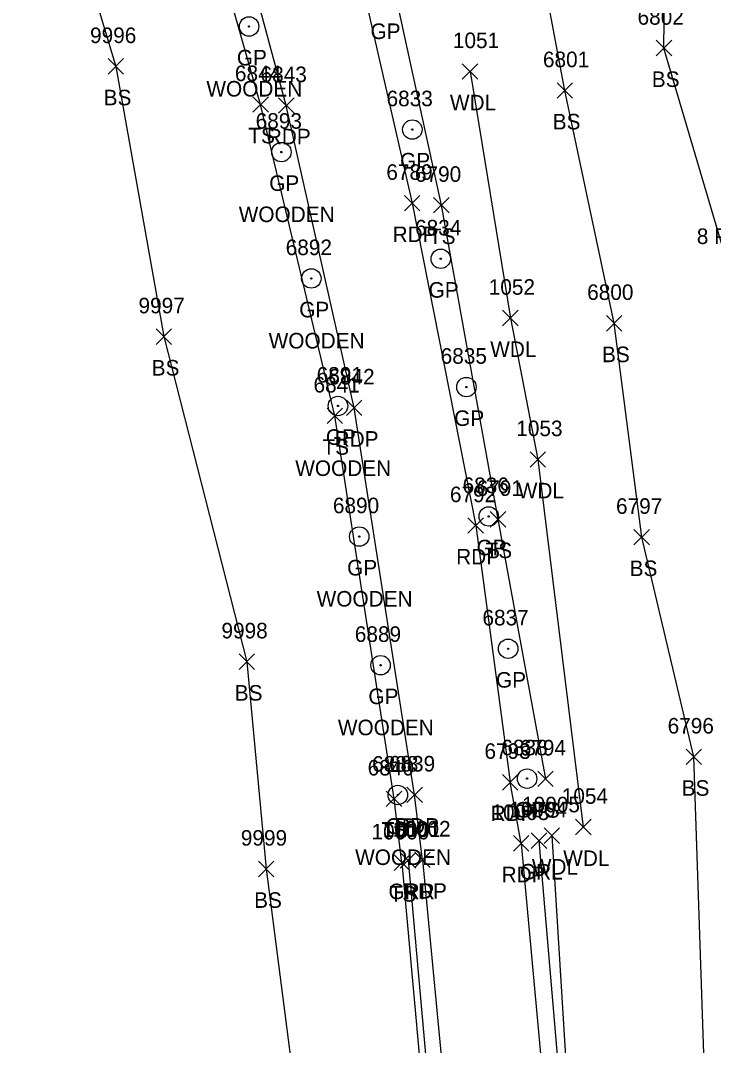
# Model space of a CAD drawing. Extents: x 1769141 to 1770817, y 735471 to 742405.
# Drawn here: x 1770054.4 to 1770143.6, y 740677.5 to 740809.3 of the extents above; entities that cross this region are included whole.
import ezdxf

# ---------------------------------------------------------------- set-up
doc = ezdxf.new("R2010")
doc.units = 0
for name, color, linetype in [('D_C', 7, 'Continuous'), ('L_A', 7, 'Continuous'), ('L_I', 7, 'Continuous'), ('L_TIC', 7, 'Continuous'), ('LAWA', 7, 'Continuous'), ('LELB', 7, 'Continuous'), ('P_A', 7, 'Continuous'), ('P_I', 7, 'Continuous'), ('P_TIC', 7, 'Continuous'), ('PET', 7, 'Continuous'), ('R_A', 7, 'Continuous'), ('R_C', 7, 'Continuous'), ('R_I', 7, 'Continuous'), ('R_TIC', 7, 'Continuous'), ('RGP', 7, 'Continuous'), ('RGR', 7, 'Continuous')]:
    doc.layers.add(name, color=color, linetype=linetype)

msp = doc.modelspace()

# ---------------------------------------------------------------- linework, layer by layer
at = {"layer": 'L_TIC'}
for points in [[(1770136.19, 740804.72), (1770138.19, 740806.72)], [(1770138.19, 740804.72), (1770136.19, 740806.72)], [(1770065.7, 740802.36), (1770067.7, 740804.36)], [(1770067.7, 740802.36), (1770065.7, 740804.36)], [(1770111.26, 740801.71), (1770113.26, 740803.71)], [(1770113.26, 740801.71), (1770111.26, 740803.71)], [(1770123.45, 740799.26), (1770125.45, 740801.26)], [(1770125.45, 740799.26), (1770123.45, 740801.26)], [(1770084.33, 740797.47), (1770086.33, 740799.47)], [(1770086.33, 740797.47), (1770084.33, 740799.47)], [(1770107.56, 740784.52), (1770109.56, 740786.52)], [(1770109.56, 740784.52), (1770107.56, 740786.52)], [(1770116.44, 740770.01), (1770118.44, 740772.01)], [(1770118.44, 740770.01), (1770116.44, 740772.01)], [(1770129.79, 740769.34), (1770131.79, 740771.34)], [(1770131.79, 740769.34), (1770129.79, 740771.34)], [(1770071.88, 740767.62), (1770073.88, 740769.62)], [(1770073.88, 740767.62), (1770071.88, 740769.62)], [(1770093.87, 740757.44), (1770095.87, 740759.44)], [(1770095.87, 740757.44), (1770093.87, 740759.44)], [(1770119.98, 740751.83), (1770121.98, 740753.83)], [(1770121.98, 740751.83), (1770119.98, 740753.83)], [(1770114.84, 740744.15), (1770116.84, 740746.15)], [(1770116.84, 740744.15), (1770114.84, 740746.15)], [(1770133.34, 740741.84), (1770135.34, 740743.84)], [(1770135.34, 740741.84), (1770133.34, 740743.84)], [(1770082.55, 740725.83), (1770084.55, 740727.83)], [(1770084.55, 740725.83), (1770082.55, 740727.83)], [(1770140.03, 740713.6), (1770142.03, 740715.6)], [(1770142.03, 740713.6), (1770140.03, 740715.6)], [(1770120.96, 740710.78), (1770122.96, 740712.78)], [(1770122.96, 740710.78), (1770120.96, 740712.78)], [(1770101.49, 740708.21), (1770103.49, 740710.21)], [(1770103.49, 740708.21), (1770101.49, 740710.21)], [(1770125.82, 740704.57), (1770127.82, 740706.57)], [(1770127.82, 740704.57), (1770125.82, 740706.57)], [(1770121.78, 740703.47), (1770123.78, 740705.47)], [(1770123.78, 740703.47), (1770121.78, 740705.47)], [(1770102.5, 740699.99), (1770104.5, 740701.99)], [(1770104.5, 740699.99), (1770102.5, 740701.99)], [(1770085.04, 740699.19), (1770087.04, 740701.19)], [(1770087.04, 740699.19), (1770085.04, 740701.19)]]:
    msp.add_lwpolyline(points, dxfattribs=at)
at = {"layer": 'LAWA'}
for points in [[(1770112.26, 740802.71), (1770117.44, 740771.01), (1770120.98, 740752.83), (1770126.82, 740705.57)], [(1770122.78, 740704.47), (1770125.57, 740659.44), (1770128.91, 740609.51), (1770131.96, 740548.28), (1770134.59, 740515.3), (1770138.96, 740463.85), (1770139.39, 740413.76), (1770142.68, 740366.71)]]:
    msp.add_lwpolyline(points, dxfattribs=at)
at = {"layer": 'LELB'}
for points in [[(1770102.49, 740709.21), (1770094.87, 740758.44), (1770085.33, 740798.47), (1770075.52, 740832.9), (1770071.79, 740852.56), (1770072, 740876.01), (1770079.42, 740895.94), (1770093.05, 740914.5), (1770103.42, 740925.63), (1770113.67, 740937.45), (1770115.5, 740958.52), (1770111.47, 740971.26), (1770103.86, 740991.31), (1770100.12, 740990.08), (1770106.06, 740964.67), (1770081.1, 740972.36)], [(1770108.26, 740894.78), (1770100.32, 740878.33), (1770097.64, 740862.66), (1770097.24, 740845.39), (1770100.42, 740822.73), (1770108.56, 740785.52), (1770115.84, 740745.15), (1770121.96, 740711.78)], [(1770148.83, 740712.41), (1770150.08, 740742.88), (1770146.81, 740773.11), (1770137.19, 740805.72), (1770137.5, 740834.46), (1770138.56, 740856.82)], [(1770054.44, 740844.19), (1770066.7, 740803.36)], [(1770141.03, 740714.6), (1770134.34, 740742.84), (1770130.79, 740770.34), (1770124.45, 740800.26), (1770118.37, 740832.68)], [(1770066.7, 740803.36), (1770072.88, 740768.62), (1770083.55, 740726.83), (1770086.04, 740700.19), (1770091.3, 740659.33), (1770094.84, 740607.83), (1770101.29, 740550.76), (1770100.94, 740526.31), (1770108.94, 740460.58), (1770110.98, 740412.54), (1770110.87, 740385.04), (1770097.8, 740370.51)], [(1770143.11, 740653.52), (1770141.03, 740714.6)], [(1770103.5, 740700.99), (1770102.49, 740709.21)], [(1770103.5, 740700.99), (1770107.28, 740658.82), (1770110.09, 740608.58), (1770112.97, 740550.02), (1770115.09, 740514.48), (1770117.12, 740463.09), (1770118.41, 740412.76)]]:
    msp.add_lwpolyline(points, dxfattribs=at)
at = {"layer": 'P_TIC'}
for points in [[(1770087.63, 740797.34), (1770089.63, 740799.34)], [(1770089.63, 740797.34), (1770087.63, 740799.34)], [(1770103.81, 740784.78), (1770105.81, 740786.78)], [(1770105.81, 740784.78), (1770103.81, 740786.78)], [(1770096.35, 740758.47), (1770098.35, 740760.47)], [(1770098.35, 740758.47), (1770096.35, 740760.47)], [(1770111.98, 740743.34), (1770113.98, 740745.34)], [(1770113.98, 740743.34), (1770111.98, 740745.34)], [(1770116.42, 740710.34), (1770118.42, 740712.34)], [(1770118.42, 740710.34), (1770116.42, 740712.34)], [(1770104.13, 740708.72), (1770106.13, 740710.72)], [(1770106.13, 740708.72), (1770104.13, 740710.72)], [(1770117.83, 740702.48), (1770119.83, 740704.48)], [(1770119.83, 740702.48), (1770117.83, 740704.48)], [(1770105.14, 740700.36), (1770107.14, 740702.36)], [(1770107.14, 740700.36), (1770105.14, 740702.36)]]:
    msp.add_lwpolyline(points, dxfattribs=at)
at = {"layer": 'PET'}
for points in [[(1770105.13, 740709.72), (1770097.35, 740759.47), (1770088.63, 740798.34), (1770079.18, 740833.38), (1770075.73, 740850.43), (1770075.74, 740874.63), (1770082.21, 740893.72), (1770094.91, 740911.6)], [(1770105.78, 740897.9), (1770097.22, 740882.49), (1770093.23, 740863.22), (1770093.28, 740846.48), (1770097.27, 740818.78), (1770104.81, 740785.78), (1770112.98, 740744.34), (1770117.42, 740711.34)], [(1770118.83, 740703.48), (1770117.42, 740711.34)], [(1770106.14, 740701.36), (1770105.13, 740709.72)], [(1770118.83, 740703.48), (1770122.85, 740659.67), (1770125.57, 740609.37), (1770128.65, 740548.21), (1770130.22, 740515.08), (1770132.68, 740464.53), (1770135.18, 740413.13), (1770137.79, 740366.92)], [(1770106.14, 740701.36), (1770110.18, 740659.08), (1770112.94, 740608.4), (1770116.08, 740549.79), (1770117.88, 740514.91), (1770120.38, 740463.02), (1770123.02, 740413.12), (1770124.14, 740391.24), (1770126.21, 740354.16)]]:
    msp.add_lwpolyline(points, dxfattribs=at)
at = {"layer": 'R_TIC'}
for points in [[(1770120.12, 740702.83), (1770122.12, 740704.83)], [(1770122.12, 740702.83), (1770120.12, 740704.83)], [(1770103.28, 740700.3), (1770105.28, 740702.3)], [(1770105.28, 740700.3), (1770103.28, 740702.3)]]:
    msp.add_lwpolyline(points, dxfattribs=at)
at = {"layer": 'RGP'}
for p, q in [((1770083.84, 740808.49), (1770083.84, 740808.49)), ((1770104.83, 740795.24), (1770104.83, 740795.24)), ((1770088, 740792.35), (1770088, 740792.35)), ((1770108.49, 740778.63), (1770108.49, 740778.63)), ((1770091.85, 740776.1), (1770091.85, 740776.1)), ((1770111.79, 740762.14), (1770111.79, 740762.14)), ((1770095.27, 740759.71), (1770095.27, 740759.71)), ((1770114.66, 740745.51), (1770114.66, 740745.51)), ((1770098.01, 740742.92), (1770098.01, 740742.92)), ((1770117.16, 740728.5), (1770117.16, 740728.5)), ((1770100.75, 740726.38), (1770100.75, 740726.38)), ((1770119.59, 740711.8), (1770119.59, 740711.8)), ((1770102.97, 740709.7), (1770102.97, 740709.7))]:
    msp.add_line(p, q, dxfattribs=at)
for centre, radius in [((1770083.84, 740808.49), 1.25), ((1770083.84, 740808.49), 0.0833), ((1770104.83, 740795.24), 1.25), ((1770104.83, 740795.24), 0.0833), ((1770088, 740792.35), 1.25), ((1770088, 740792.35), 0.0833), ((1770108.49, 740778.63), 1.25), ((1770108.49, 740778.63), 0.0833), ((1770091.85, 740776.1), 1.25), ((1770091.85, 740776.1), 0.0833), ((1770111.79, 740762.14), 1.25), ((1770111.79, 740762.14), 0.0833), ((1770095.27, 740759.71), 1.25), ((1770095.27, 740759.71), 0.0833), ((1770114.66, 740745.51), 1.25), ((1770114.66, 740745.51), 0.0833), ((1770098.01, 740742.92), 1.25), ((1770098.01, 740742.92), 0.0833), ((1770117.16, 740728.5), 1.25), ((1770117.16, 740728.5), 0.0833), ((1770100.75, 740726.38), 1.25), ((1770100.75, 740726.38), 0.0833), ((1770119.59, 740711.8), 1.25), ((1770102.97, 740709.7), 1.25), ((1770119.59, 740711.8), 0.0833), ((1770102.97, 740709.7), 0.0833)]:
    msp.add_circle(centre, radius, dxfattribs=at)
at = {"layer": 'RGR'}
for points in [[(1770121.12, 740703.83), (1770124.89, 740659.66), (1770127.38, 740609.54), (1770130.69, 740548.36), (1770132.41, 740515.26), (1770135.66, 740464.82), (1770137.42, 740413.55), (1770140, 740367.83)], [(1770104.28, 740701.3), (1770108.06, 740659.13), (1770111.14, 740608.55), (1770114.23, 740549.9), (1770116.09, 740514.54), (1770118.42, 740463.29), (1770120.8, 740413.18)]]:
    msp.add_lwpolyline(points, dxfattribs=at)

# ---------------------------------------------------------------- texts
at = {"layer": 'D_C'}
msp.add_text('8 PLASTIC', height=2, dxfattribs=at).set_placement((1770141.42, 740780.53))
at = {"layer": 'L_A'}
for s, p in [('BS', (1770135.63, 740800.72)), ('BS', (1770065.14, 740798.36)), ('WDL', (1770109.67, 740797.71)), ('BS', (1770122.89, 740795.26)), ('TS', (1770083.74, 740793.47)), ('TS', (1770106.97, 740780.52)), ('WDL', (1770114.85, 740766.01)), ('BS', (1770129.23, 740765.34)), ('BS', (1770071.32, 740763.62)), ('TS', (1770093.28, 740753.44)), ('WDL', (1770118.39, 740747.83)), ('TS', (1770114.25, 740740.15)), ('BS', (1770132.78, 740737.84)), ('BS', (1770082, 740721.83)), ('BS', (1770139.47, 740709.6)), ('TS', (1770120.37, 740706.78)), ('TS', (1770100.89, 740704.21)), ('WDL', (1770124.24, 740700.57)), ('WDL', (1770120.2, 740699.47)), ('TS', (1770101.91, 740695.99)), ('BS', (1770084.49, 740695.19))]:
    msp.add_text(s, height=2, dxfattribs=at).set_placement(p)
at = {"layer": 'L_I'}
for s, p in [('6802', (1770133.8, 740808.72)), ('9996', (1770063.39, 740806.36)), ('1051', (1770110.05, 740805.71)), ('6801', (1770121.63, 740803.26)), ('6844', (1770082.02, 740801.47)), ('6790', (1770105.17, 740788.52)), ('1052', (1770114.66, 740774.01)), ('6800', (1770127.32, 740773.34)), ('9997', (1770069.62, 740771.62)), ('6841', (1770092.13, 740761.44)), ('1053', (1770118.2, 740755.83)), ('6791', (1770113.1, 740748.15)), ('6797', (1770131.03, 740745.84)), ('9998', (1770080.29, 740729.83)), ('6796', (1770137.67, 740717.6)), ('6794', (1770118.65, 740714.78)), ('6840', (1770099.09, 740712.21)), ('10005', (1770118.95, 740707.47)), ('1054', (1770124.05, 740708.57)), ('10000', (1770099.59, 740703.99)), ('9999', (1770082.78, 740703.19))]:
    msp.add_text(s, height=2, dxfattribs=at).set_placement(p)
at = {"layer": 'P_A'}
for p in [(1770086.12, 740793.34), (1770102.3, 740780.78), (1770094.84, 740754.47), (1770110.47, 740739.34), (1770114.91, 740706.34), (1770102.62, 740704.72), (1770116.32, 740698.48), (1770103.63, 740696.36)]:
    msp.add_text('RDP', height=2, dxfattribs=at).set_placement(p)
at = {"layer": 'P_I'}
for s, p in [('6843', (1770085.32, 740801.34)), ('6789', (1770101.49, 740788.78)), ('6842', (1770094.04, 740762.47)), ('6792', (1770109.67, 740747.34)), ('6793', (1770114.11, 740714.34)), ('6839', (1770101.82, 740712.72)), ('10003', (1770115.01, 740706.48)), ('10002', (1770102.32, 740704.36))]:
    msp.add_text(s, height=2, dxfattribs=at).set_placement(p)
at = {"layer": 'R_A'}
for s, p in [('GP', (1770099.46, 740806.88)), ('GP', (1770082.27, 740803.49)), ('GP', (1770103.26, 740790.24)), ('GP', (1770086.43, 740787.35)), ('GP', (1770106.93, 740773.63)), ('GP', (1770090.29, 740771.1)), ('GP', (1770110.22, 740757.14)), ('GP', (1770093.71, 740754.71)), ('GP', (1770113.1, 740740.51)), ('GP', (1770096.45, 740737.92)), ('GP', (1770115.59, 740723.5)), ('GP', (1770099.18, 740721.38)), ('GP', (1770118.02, 740706.8)), ('GP', (1770101.4, 740704.7)), ('GRL', (1770118.67, 740698.83)), ('GRR', (1770101.77, 740696.3))]:
    msp.add_text(s, height=2, dxfattribs=at).set_placement(p)
at = {"layer": 'R_C'}
for p in [(1770078.35, 740799.49), (1770082.51, 740783.35), (1770086.36, 740767.1), (1770089.78, 740750.71), (1770092.53, 740733.92), (1770095.26, 740717.38), (1770097.48, 740700.7)]:
    msp.add_text('WOODEN', height=2, dxfattribs=at).set_placement(p)
at = {"layer": 'R_I'}
for s, p in [('6833', (1770101.52, 740798.24)), ('6893', (1770084.69, 740795.35)), ('6834', (1770105.19, 740781.63)), ('6892', (1770088.55, 740779.1)), ('6835', (1770108.48, 740765.14)), ('6891', (1770092.53, 740762.71)), ('6836', (1770111.3, 740748.51)), ('6890', (1770094.62, 740745.92)), ('6837', (1770113.85, 740731.5)), ('6889', (1770097.44, 740729.38)), ('6838', (1770116.28, 740714.8)), ('6888', (1770099.66, 740712.7)), ('10004', (1770117.3, 740706.83)), ('10001', (1770101.02, 740704.3))]:
    msp.add_text(s, height=2, dxfattribs=at).set_placement(p)

doc.saveas('drawing.dxf')
